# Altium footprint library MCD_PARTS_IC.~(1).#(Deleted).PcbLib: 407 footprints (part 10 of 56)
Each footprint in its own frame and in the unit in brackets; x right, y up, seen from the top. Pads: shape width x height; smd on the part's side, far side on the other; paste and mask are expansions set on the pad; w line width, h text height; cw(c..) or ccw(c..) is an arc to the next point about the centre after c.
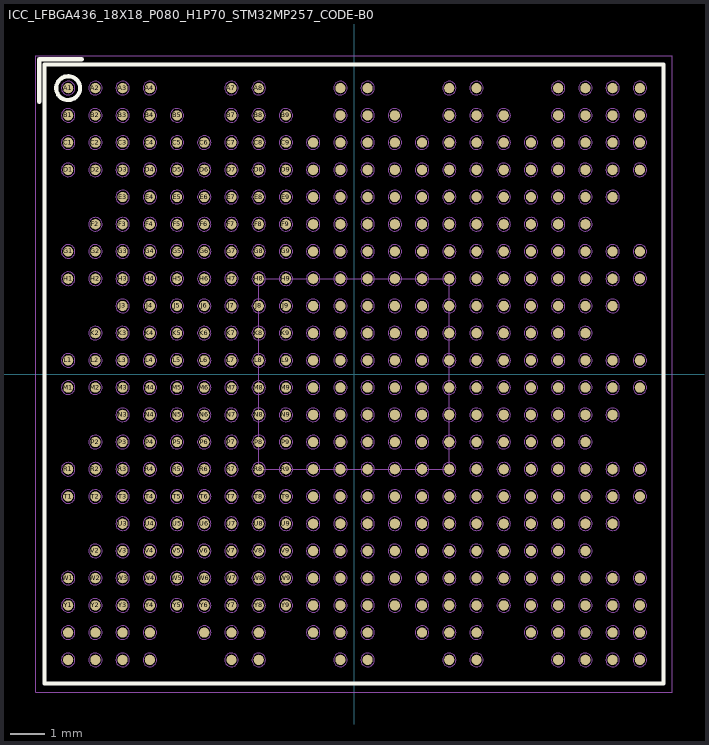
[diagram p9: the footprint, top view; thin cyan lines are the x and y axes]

## ICC_LFBGA436_18X18_P080_H1P70_STM32MP257_CODE-B0D1 [mm] "MCD02000"
height 1.7
pads (436):
  round 0.3 smd paste+0.025 mask+0.05: A1(-8.4,8.4) A2(-7.6,8.4) A3(-6.8,8.4) A4(-6,8.4) A7(-3.6,8.4) A8(-2.8,8.4) A11(-0.4,8.4) A12(0.4,8.4) A15(2.8,8.4) A16(3.6,8.4) A19(6,8.4) A20(6.8,8.4) A21(7.6,8.4) A22(8.4,8.4) AA1(-8.4,-7.6) AA2(-7.6,-7.6) AA3(-6.8,-7.6) AA4(-6,-7.6) AA6(-4.4,-7.6) AA7(-3.6,-7.6) AA8(-2.8,-7.6) AA10(-1.2,-7.6) AA11(-0.4,-7.6) AA12(0.4,-7.6) AA14(2,-7.6) AA15(2.8,-7.6) AA16(3.6,-7.6) AA18(5.2,-7.6) AA19(6,-7.6) AA20(6.8,-7.6) AA21(7.6,-7.6) AA22(8.4,-7.6) AB1(-8.4,-8.4) AB2(-7.6,-8.4) AB3(-6.8,-8.4) AB4(-6,-8.4) AB7(-3.6,-8.4) AB8(-2.8,-8.4) AB11(-0.4,-8.4) AB12(0.4,-8.4) AB15(2.8,-8.4) AB16(3.6,-8.4) AB19(6,-8.4) AB20(6.8,-8.4) AB21(7.6,-8.4) AB22(8.4,-8.4) B1(-8.4,7.6) B2(-7.6,7.6) B3(-6.8,7.6) B4(-6,7.6) B5(-5.2,7.6) B7(-3.6,7.6) B8(-2.8,7.6) B9(-2,7.6) B11(-0.4,7.6) B12(0.4,7.6) B13(1.2,7.6) B15(2.8,7.6) B16(3.6,7.6) B17(4.4,7.6) B19(6,7.6) B20(6.8,7.6) B21(7.6,7.6) B22(8.4,7.6) C1(-8.4,6.8) C2(-7.6,6.8) C3(-6.8,6.8) C4(-6,6.8) C5(-5.2,6.8) C6(-4.4,6.8) C7(-3.6,6.8) C8(-2.8,6.8) C9(-2,6.8) C10(-1.2,6.8) C11(-0.4,6.8) C12(0.4,6.8) C13(1.2,6.8) C14(2,6.8) C15(2.8,6.8) C16(3.6,6.8) C17(4.4,6.8) C18(5.2,6.8) C19(6,6.8) C20(6.8,6.8) C21(7.6,6.8) C22(8.4,6.8) D1(-8.4,6) D2(-7.6,6) D3(-6.8,6) D4(-6,6) D5(-5.2,6) D6(-4.4,6) D7(-3.6,6) D8(-2.8,6) D9(-2,6) D10(-1.2,6) D11(-0.4,6) D12(0.4,6) D13(1.2,6) D14(2,6) D15(2.8,6) D16(3.6,6) D17(4.4,6) D18(5.2,6) D19(6,6) D20(6.8,6) D21(7.6,6) D22(8.4,6) E3(-6.8,5.2) E4(-6,5.2) E5(-5.2,5.2) E6(-4.4,5.2) E7(-3.6,5.2) E8(-2.8,5.2) E9(-2,5.2) E10(-1.2,5.2) E11(-0.4,5.2) E12(0.4,5.2) E13(1.2,5.2) E14(2,5.2) E15(2.8,5.2) E16(3.6,5.2) E17(4.4,5.2) E18(5.2,5.2) E19(6,5.2) E20(6.8,5.2) E21(7.6,5.2) F2(-7.6,4.4) F3(-6.8,4.4) F4(-6,4.4) F5(-5.2,4.4) F6(-4.4,4.4) F7(-3.6,4.4) F8(-2.8,4.4) F9(-2,4.4) F10(-1.2,4.4) F11(-0.4,4.4) F12(0.4,4.4) F13(1.2,4.4) F14(2,4.4) F15(2.8,4.4) F16(3.6,4.4) F17(4.4,4.4) F18(5.2,4.4) F19(6,4.4) F20(6.8,4.4) G1(-8.4,3.6) G2(-7.6,3.6) G3(-6.8,3.6) G4(-6,3.6) G5(-5.2,3.6) G6(-4.4,3.6) G7(-3.6,3.6) G8(-2.8,3.6) G9(-2,3.6) G10(-1.2,3.6) G11(-0.4,3.6) G12(0.4,3.6) G13(1.2,3.6) G14(2,3.6) G15(2.8,3.6) G16(3.6,3.6) G17(4.4,3.6) G18(5.2,3.6) G19(6,3.6) G20(6.8,3.6) G21(7.6,3.6) G22(8.4,3.6) H1(-8.4,2.8) H2(-7.6,2.8) H3(-6.8,2.8) H4(-6,2.8) H5(-5.2,2.8) H6(-4.4,2.8) H7(-3.6,2.8) H8(-2.8,2.8) H9(-2,2.8) H10(-1.2,2.8) H11(-0.4,2.8) H12(0.4,2.8) H13(1.2,2.8) H14(2,2.8) H15(2.8,2.8) H16(3.6,2.8) H17(4.4,2.8) H18(5.2,2.8) H19(6,2.8) H20(6.8,2.8) H21(7.6,2.8) H22(8.4,2.8) J3(-6.8,2) J4(-6,2) J5(-5.2,2) J6(-4.4,2) J7(-3.6,2) J8(-2.8,2) J9(-2,2) J10(-1.2,2) J11(-0.4,2) J12(0.4,2) J13(1.2,2) J14(2,2) J15(2.8,2) J16(3.6,2) J17(4.4,2) J18(5.2,2) J19(6,2) J20(6.8,2) J21(7.6,2) K2(-7.6,1.2) K3(-6.8,1.2) K4(-6,1.2) K5(-5.2,1.2) K6(-4.4,1.2) K7(-3.6,1.2) K8(-2.8,1.2) K9(-2,1.2) K10(-1.2,1.2) K11(-0.4,1.2) K12(0.4,1.2) K13(1.2,1.2) K14(2,1.2) K15(2.8,1.2) K16(3.6,1.2) K17(4.4,1.2) K18(5.2,1.2) K19(6,1.2) K20(6.8,1.2) L1(-8.4,0.4) L2(-7.6,0.4) L3(-6.8,0.4) L4(-6,0.4) L5(-5.2,0.4) L6(-4.4,0.4) L7(-3.6,0.4) L8(-2.8,0.4) L9(-2,0.4) L10(-1.2,0.4) L11(-0.4,0.4) L12(0.4,0.4) L13(1.2,0.4) L14(2,0.4) L15(2.8,0.4) L16(3.6,0.4) L17(4.4,0.4) L18(5.2,0.4) L19(6,0.4) L20(6.8,0.4) L21(7.6,0.4) L22(8.4,0.4) M1(-8.4,-0.4) M2(-7.6,-0.4) M3(-6.8,-0.4) M4(-6,-0.4) M5(-5.2,-0.4) M6(-4.4,-0.4) M7(-3.6,-0.4) M8(-2.8,-0.4) M9(-2,-0.4) M10(-1.2,-0.4) M11(-0.4,-0.4) M12(0.4,-0.4) M13(1.2,-0.4) M14(2,-0.4) M15(2.8,-0.4) M16(3.6,-0.4) M17(4.4,-0.4) M18(5.2,-0.4) M19(6,-0.4) M20(6.8,-0.4) M21(7.6,-0.4) M22(8.4,-0.4) N3(-6.8,-1.2) N4(-6,-1.2) N5(-5.2,-1.2) N6(-4.4,-1.2) N7(-3.6,-1.2) N8(-2.8,-1.2) N9(-2,-1.2) N10(-1.2,-1.2) N11(-0.4,-1.2) N12(0.4,-1.2) N13(1.2,-1.2) N14(2,-1.2) N15(2.8,-1.2) N16(3.6,-1.2) N17(4.4,-1.2) N18(5.2,-1.2) N19(6,-1.2) N20(6.8,-1.2) N21(7.6,-1.2) P2(-7.6,-2) P3(-6.8,-2) P4(-6,-2) P5(-5.2,-2) P6(-4.4,-2) P7(-3.6,-2) P8(-2.8,-2) P9(-2,-2) P10(-1.2,-2) P11(-0.4,-2) P12(0.4,-2) P13(1.2,-2) P14(2,-2) P15(2.8,-2) P16(3.6,-2) P17(4.4,-2) P18(5.2,-2) P19(6,-2) P20(6.8,-2) R1(-8.4,-2.8) R2(-7.6,-2.8) R3(-6.8,-2.8) R4(-6,-2.8) R5(-5.2,-2.8) R6(-4.4,-2.8) R7(-3.6,-2.8) R8(-2.8,-2.8) R9(-2,-2.8) R10(-1.2,-2.8) R11(-0.4,-2.8) R12(0.4,-2.8) R13(1.2,-2.8) R14(2,-2.8) R15(2.8,-2.8) R16(3.6,-2.8) R17(4.4,-2.8) R18(5.2,-2.8) R19(6,-2.8) R20(6.8,-2.8) R21(7.6,-2.8) R22(8.4,-2.8) T1(-8.4,-3.6) T2(-7.6,-3.6) T3(-6.8,-3.6) T4(-6,-3.6) T5(-5.2,-3.6) T6(-4.4,-3.6) T7(-3.6,-3.6) T8(-2.8,-3.6) T9(-2,-3.6) T10(-1.2,-3.6) T11(-0.4,-3.6) T12(0.4,-3.6) T13(1.2,-3.6) T14(2,-3.6) T15(2.8,-3.6) T16(3.6,-3.6) T17(4.4,-3.6) T18(5.2,-3.6) T19(6,-3.6) T20(6.8,-3.6) T21(7.6,-3.6) T22(8.4,-3.6) U3(-6.8,-4.4) U4(-6,-4.4) U5(-5.2,-4.4) U6(-4.4,-4.4) U7(-3.6,-4.4) U8(-2.8,-4.4) U9(-2,-4.4) U10(-1.2,-4.4) U11(-0.4,-4.4) U12(0.4,-4.4) U13(1.2,-4.4) U14(2,-4.4) U15(2.8,-4.4) U16(3.6,-4.4) U17(4.4,-4.4) U18(5.2,-4.4) U19(6,-4.4) U20(6.8,-4.4) U21(7.6,-4.4) V2(-7.6,-5.2) V3(-6.8,-5.2) V4(-6,-5.2) V5(-5.2,-5.2) V6(-4.4,-5.2) V7(-3.6,-5.2) V8(-2.8,-5.2) V9(-2,-5.2) V10(-1.2,-5.2) V11(-0.4,-5.2) V12(0.4,-5.2) V13(1.2,-5.2) V14(2,-5.2) V15(2.8,-5.2) V16(3.6,-5.2) V17(4.4,-5.2) V18(5.2,-5.2) V19(6,-5.2) V20(6.8,-5.2) W1(-8.4,-6) W2(-7.6,-6) W3(-6.8,-6) W4(-6,-6) W5(-5.2,-6) W6(-4.4,-6) W7(-3.6,-6) W8(-2.8,-6) W9(-2,-6) W10(-1.2,-6) W11(-0.4,-6) W12(0.4,-6) W13(1.2,-6) W14(2,-6) W15(2.8,-6) W16(3.6,-6) W17(4.4,-6) W18(5.2,-6) W19(6,-6) W20(6.8,-6) W21(7.6,-6) W22(8.4,-6) Y1(-8.4,-6.8) Y2(-7.6,-6.8) Y3(-6.8,-6.8) Y4(-6,-6.8) Y5(-5.2,-6.8) Y6(-4.4,-6.8) Y7(-3.6,-6.8) Y8(-2.8,-6.8) Y9(-2,-6.8) Y10(-1.2,-6.8) Y11(-0.4,-6.8) Y12(0.4,-6.8) Y13(1.2,-6.8) Y14(2,-6.8) Y15(2.8,-6.8) Y16(3.6,-6.8) Y17(4.4,-6.8) Y18(5.2,-6.8) Y19(6,-6.8) Y20(6.8,-6.8) Y21(7.6,-6.8) Y22(8.4,-6.8)
Top Overlay:
  circle w0.12: c-8.4,8.4 r0.35
  lines w0.12: -9.25,8 -9.25,9.25 -8,9.25 ; -9.1,-9.1 -9.1,9.1 9.1,9.1 9.1,-9.1 -9.1,-9.1
M14-Top Assembly:
  drawing of 444 lines, arcs and shapes, not listed
  text "'.Designator'" at -2,-0.2 h0.75
  text "A1" at -8.65,8.2 h0.4
  text "A22" at 7.875,8.2 h0.4
  text "AB22" at 7.7,-8.6 h0.4
  text "AB1" at -8.8,-8.6 h0.4
M16-Top Courtyard:
  lines w0.01: -9.35,-9.35 -9.35,9.35 9.35,9.35 9.35,-9.35 -9.35,-9.35
3D body: height 1.11, standoff 1.1, extent -8.697,8.101 -8.1,8.7
3D body: height 0.36, standoff -0.04, extent 2.601,4.203 3,4.597
3D body: height 0.36, standoff -0.04, extent 1.801,4.203 2.2,4.597
3D body: height 0.36, standoff -0.04, extent 1.001,4.203 1.4,4.597
3D body: height 0.36, standoff -0.04, extent 0.201,4.203 0.6,4.597
3D body: height 0.36, standoff -0.04, extent -0.599,4.203 -0.2,4.597
3D body: height 0.36, standoff -0.04, extent -4.599,4.203 -4.2,4.597
3D body: height 0.36, standoff -0.04, extent -3.799,4.203 -3.4,4.597
3D body: height 0.36, standoff -0.04, extent -2.999,4.203 -2.6,4.597
3D body: height 0.36, standoff -0.04, extent -2.199,4.203 -1.8,4.597
3D body: height 0.36, standoff -0.04, extent -1.399,4.203 -1,4.597
3D body: height 0.36, standoff -0.04, extent -7.799,4.203 -7.4,4.597
3D body: height 0.36, standoff -0.04, extent -6.999,4.203 -6.6,4.597
3D body: height 0.36, standoff -0.04, extent -6.199,4.203 -5.8,4.597
3D body: height 0.36, standoff -0.04, extent -5.399,4.203 -5,4.597
3D body: height 0.36, standoff -0.04, extent 2.601,5.003 3,5.397
3D body: height 0.36, standoff -0.04, extent 1.801,5.003 2.2,5.397
3D body: height 0.36, standoff -0.04, extent 1.001,5.003 1.4,5.397
3D body: height 0.36, standoff -0.04, extent 0.201,5.003 0.6,5.397
3D body: height 0.36, standoff -0.04, extent -0.599,5.003 -0.2,5.397
3D body: height 0.36, standoff -0.04, extent -4.599,5.003 -4.2,5.397
3D body: height 0.36, standoff -0.04, extent -3.799,5.003 -3.4,5.397
3D body: height 0.36, standoff -0.04, extent -2.999,5.003 -2.6,5.397
3D body: height 0.36, standoff -0.04, extent -2.199,5.003 -1.8,5.397
3D body: height 0.36, standoff -0.04, extent -1.399,5.003 -1,5.397
3D body: height 0.36, standoff -0.04, extent -6.999,5.003 -6.6,5.397
3D body: height 0.36, standoff -0.04, extent -6.199,5.003 -5.8,5.397
3D body: height 0.36, standoff -0.04, extent -5.399,5.003 -5,5.397
3D body: height 0.36, standoff -0.04, extent 2.601,5.803 3,6.197
3D body: height 0.36, standoff -0.04, extent 1.801,5.803 2.2,6.197
3D body: height 0.36, standoff -0.04, extent 1.001,5.803 1.4,6.197
3D body: height 0.36, standoff -0.04, extent 0.201,5.803 0.6,6.197
3D body: height 0.36, standoff -0.04, extent -0.599,5.803 -0.2,6.197
3D body: height 0.36, standoff -0.04, extent -4.599,5.803 -4.2,6.197
3D body: height 0.36, standoff -0.04, extent -3.799,5.803 -3.4,6.197
3D body: height 0.36, standoff -0.04, extent -2.999,5.803 -2.6,6.197
3D body: height 0.36, standoff -0.04, extent -2.199,5.803 -1.8,6.197
3D body: height 0.36, standoff -0.04, extent -1.399,5.803 -1,6.197
3D body: height 0.36, standoff -0.04, extent -8.599,5.803 -8.2,6.197
3D body: height 0.36, standoff -0.04, extent -7.799,5.803 -7.4,6.197
3D body: height 0.36, standoff -0.04, extent -6.999,5.803 -6.6,6.197
3D body: height 0.36, standoff -0.04, extent -6.199,5.803 -5.8,6.197
3D body: height 0.36, standoff -0.04, extent -5.399,5.803 -5,6.197
3D body: height 0.36, standoff -0.04, extent 2.601,6.603 3,6.997
3D body: height 0.36, standoff -0.04, extent 1.801,6.603 2.2,6.997
3D body: height 0.36, standoff -0.04, extent 1.001,6.603 1.4,6.997
3D body: height 0.36, standoff -0.04, extent 0.201,6.603 0.6,6.997
3D body: height 0.36, standoff -0.04, extent -0.599,6.603 -0.2,6.997
3D body: height 0.36, standoff -0.04, extent -4.599,6.603 -4.2,6.997
3D body: height 0.36, standoff -0.04, extent -3.799,6.603 -3.4,6.997
3D body: height 0.36, standoff -0.04, extent -2.999,6.603 -2.6,6.997
3D body: height 0.36, standoff -0.04, extent -2.199,6.603 -1.8,6.997
3D body: height 0.36, standoff -0.04, extent -1.399,6.603 -1,6.997
3D body: height 0.36, standoff -0.04, extent -8.599,6.603 -8.2,6.997
3D body: height 0.36, standoff -0.04, extent -7.799,6.603 -7.4,6.997
3D body: height 0.36, standoff -0.04, extent -6.999,6.603 -6.6,6.997
3D body: height 0.36, standoff -0.04, extent -6.199,6.603 -5.8,6.997
3D body: height 0.36, standoff -0.04, extent -5.399,6.603 -5,6.997
3D body: height 0.36, standoff -0.04, extent 2.601,7.403 3,7.797
3D body: height 0.36, standoff -0.04, extent 1.001,7.403 1.4,7.797
3D body: height 0.36, standoff -0.04, extent 0.201,7.403 0.6,7.797
3D body: height 0.36, standoff -0.04, extent -0.599,7.403 -0.2,7.797
3D body: height 0.36, standoff -0.04, extent -3.799,7.403 -3.4,7.797
3D body: height 0.36, standoff -0.04, extent -2.999,7.403 -2.6,7.797
3D body: height 0.36, standoff -0.04, extent -2.199,7.403 -1.8,7.797
3D body: height 0.36, standoff -0.04, extent -8.599,7.403 -8.2,7.797
3D body: height 0.36, standoff -0.04, extent -7.799,7.403 -7.4,7.797
3D body: height 0.36, standoff -0.04, extent -6.999,7.403 -6.6,7.797
3D body: height 0.36, standoff -0.04, extent -6.199,7.403 -5.8,7.797
3D body: height 0.36, standoff -0.04, extent -5.399,7.403 -5,7.797
3D body: height 0.36, standoff -0.04, extent -8.599,8.203 -8.2,8.597
3D body: height 0.36, standoff -0.04, extent -6.199,8.203 -5.8,8.597
3D body: height 0.36, standoff -0.04, extent -6.999,8.203 -6.6,8.597
3D body: height 0.36, standoff -0.04, extent -7.799,8.203 -7.4,8.597
3D body: height 0.36, standoff -0.04, extent -2.999,8.203 -2.6,8.597
3D body: height 0.36, standoff -0.04, extent -3.799,8.203 -3.4,8.597
3D body: height 0.36, standoff -0.04, extent -0.599,8.203 -0.2,8.597
3D body: height 0.36, standoff -0.04, extent 0.201,8.203 0.6,8.597
3D body: height 0.36, standoff -0.04, extent 2.601,8.203 3,8.597
3D body: height 0.36, standoff -0.04, extent 4.201,4.203 4.6,4.597
3D body: height 0.36, standoff -0.04, extent 5.001,4.203 5.4,4.597
3D body: height 0.36, standoff -0.04, extent 5.801,4.203 6.2,4.597
3D body: height 0.36, standoff -0.04, extent 3.401,5.003 3.8,5.397
3D body: height 0.36, standoff -0.04, extent 4.201,5.003 4.6,5.397
3D body: height 0.36, standoff -0.04, extent 5.001,5.003 5.4,5.397
3D body: height 0.36, standoff -0.04, extent 3.401,5.803 3.8,6.197
3D body: height 0.36, standoff -0.04, extent 4.201,5.803 4.6,6.197
3D body: height 0.36, standoff -0.04, extent 5.001,5.803 5.4,6.197
3D body: height 0.36, standoff -0.04, extent 5.801,5.803 6.2,6.197
3D body: height 0.36, standoff -0.04, extent 3.401,6.603 3.8,6.997
3D body: height 0.36, standoff -0.04, extent 4.201,6.603 4.6,6.997
3D body: height 0.36, standoff -0.04, extent 5.001,6.603 5.4,6.997
3D body: height 0.36, standoff -0.04, extent 5.801,6.603 6.2,6.997
3D body: height 0.36, standoff -0.04, extent 3.401,7.403 3.8,7.797
3D body: height 0.36, standoff -0.04, extent 4.201,7.403 4.6,7.797
3D body: height 0.36, standoff -0.04, extent 5.801,7.403 6.2,7.797
3D body: height 0.36, standoff -0.04, extent 5.801,8.203 6.2,8.597
3D body: height 0.36, standoff -0.04, extent 3.401,8.203 3.8,8.597
3D body: height 0.36, standoff -0.04, extent 2.601,-0.597 3,-0.203
3D body: height 0.36, standoff -0.04, extent 1.801,-0.597 2.2,-0.203
3D body: height 0.36, standoff -0.04, extent 1.001,-0.597 1.4,-0.203
3D body: height 0.36, standoff -0.04, extent 0.201,-0.597 0.6,-0.203
3D body: height 0.36, standoff -0.04, extent -0.599,-0.597 -0.2,-0.203
3D body: height 0.36, standoff -0.04, extent -4.599,-0.597 -4.2,-0.203
3D body: height 0.36, standoff -0.04, extent -3.799,-0.597 -3.4,-0.203
3D body: height 0.36, standoff -0.04, extent -2.999,-0.597 -2.6,-0.203
3D body: height 0.36, standoff -0.04, extent -2.199,-0.597 -1.8,-0.203
3D body: height 0.36, standoff -0.04, extent -1.399,-0.597 -1,-0.203
3D body: height 0.36, standoff -0.04, extent -8.599,-0.597 -8.2,-0.203
3D body: height 0.36, standoff -0.04, extent -7.799,-0.597 -7.4,-0.203
3D body: height 0.36, standoff -0.04, extent -6.999,-0.597 -6.6,-0.203
3D body: height 0.36, standoff -0.04, extent -6.199,-0.597 -5.8,-0.203
3D body: height 0.36, standoff -0.04, extent -5.399,-0.597 -5,-0.203
3D body: height 0.36, standoff -0.04, extent 2.601,0.203 3,0.597
3D body: height 0.36, standoff -0.04, extent 1.801,0.203 2.2,0.597
3D body: height 0.36, standoff -0.04, extent 1.001,0.203 1.4,0.597
3D body: height 0.36, standoff -0.04, extent 0.201,0.203 0.6,0.597
3D body: height 0.36, standoff -0.04, extent -0.599,0.203 -0.2,0.597
3D body: height 0.36, standoff -0.04, extent -4.599,0.203 -4.2,0.597
3D body: height 0.36, standoff -0.04, extent -3.799,0.203 -3.4,0.597
3D body: height 0.36, standoff -0.04, extent -2.999,0.203 -2.6,0.597
3D body: height 0.36, standoff -0.04, extent -2.199,0.203 -1.8,0.597
3D body: height 0.36, standoff -0.04, extent -1.399,0.203 -1,0.597
3D body: height 0.36, standoff -0.04, extent -8.599,0.203 -8.2,0.597
3D body: height 0.36, standoff -0.04, extent -7.799,0.203 -7.4,0.597
3D body: height 0.36, standoff -0.04, extent -6.999,0.203 -6.6,0.597
3D body: height 0.36, standoff -0.04, extent -6.199,0.203 -5.8,0.597
3D body: height 0.36, standoff -0.04, extent -5.399,0.203 -5,0.597
3D body: height 0.36, standoff -0.04, extent 2.601,1.003 3,1.397
3D body: height 0.36, standoff -0.04, extent 1.801,1.003 2.2,1.397
3D body: height 0.36, standoff -0.04, extent 1.001,1.003 1.4,1.397
3D body: height 0.36, standoff -0.04, extent 0.201,1.003 0.6,1.397
3D body: height 0.36, standoff -0.04, extent -0.599,1.003 -0.2,1.397
3D body: height 0.36, standoff -0.04, extent -4.599,1.003 -4.2,1.397
3D body: height 0.36, standoff -0.04, extent -3.799,1.003 -3.4,1.397
3D body: height 0.36, standoff -0.04, extent -2.999,1.003 -2.6,1.397
3D body: height 0.36, standoff -0.04, extent -2.199,1.003 -1.8,1.397
3D body: height 0.36, standoff -0.04, extent -1.399,1.003 -1,1.397
3D body: height 0.36, standoff -0.04, extent -7.799,1.003 -7.4,1.397
3D body: height 0.36, standoff -0.04, extent -6.999,1.003 -6.6,1.397
3D body: height 0.36, standoff -0.04, extent -6.199,1.003 -5.8,1.397
3D body: height 0.36, standoff -0.04, extent -5.399,1.003 -5,1.397
3D body: height 0.36, standoff -0.04, extent 2.601,1.803 3,2.197
3D body: height 0.36, standoff -0.04, extent 1.801,1.803 2.2,2.197
3D body: height 0.36, standoff -0.04, extent 1.001,1.803 1.4,2.197
3D body: height 0.36, standoff -0.04, extent 0.201,1.803 0.6,2.197
3D body: height 0.36, standoff -0.04, extent -0.599,1.803 -0.2,2.197
3D body: height 0.36, standoff -0.04, extent -4.599,1.803 -4.2,2.197
3D body: height 0.36, standoff -0.04, extent -3.799,1.803 -3.4,2.197
3D body: height 0.36, standoff -0.04, extent -2.999,1.803 -2.6,2.197
3D body: height 0.36, standoff -0.04, extent -2.199,1.803 -1.8,2.197
3D body: height 0.36, standoff -0.04, extent -1.399,1.803 -1,2.197
3D body: height 0.36, standoff -0.04, extent -6.999,1.803 -6.6,2.197
3D body: height 0.36, standoff -0.04, extent -6.199,1.803 -5.8,2.197
3D body: height 0.36, standoff -0.04, extent -5.399,1.803 -5,2.197
3D body: height 0.36, standoff -0.04, extent 2.601,2.603 3,2.997
3D body: height 0.36, standoff -0.04, extent 1.801,2.603 2.2,2.997
3D body: height 0.36, standoff -0.04, extent 1.001,2.603 1.4,2.997
3D body: height 0.36, standoff -0.04, extent 0.201,2.603 0.6,2.997
3D body: height 0.36, standoff -0.04, extent -0.599,2.603 -0.2,2.997
3D body: height 0.36, standoff -0.04, extent -4.599,2.603 -4.2,2.997
3D body: height 0.36, standoff -0.04, extent -3.799,2.603 -3.4,2.997
3D body: height 0.36, standoff -0.04, extent -2.999,2.603 -2.6,2.997
3D body: height 0.36, standoff -0.04, extent -2.199,2.603 -1.8,2.997
3D body: height 0.36, standoff -0.04, extent -1.399,2.603 -1,2.997
3D body: height 0.36, standoff -0.04, extent -8.599,2.603 -8.2,2.997
3D body: height 0.36, standoff -0.04, extent -7.799,2.603 -7.4,2.997
3D body: height 0.36, standoff -0.04, extent -6.999,2.603 -6.6,2.997
3D body: height 0.36, standoff -0.04, extent -6.199,2.603 -5.8,2.997
3D body: height 0.36, standoff -0.04, extent -5.399,2.603 -5,2.997
3D body: height 0.36, standoff -0.04, extent -5.399,3.403 -5,3.797
3D body: height 0.36, standoff -0.04, extent -6.199,3.403 -5.8,3.797
3D body: height 0.36, standoff -0.04, extent -6.999,3.403 -6.6,3.797
3D body: height 0.36, standoff -0.04, extent -7.799,3.403 -7.4,3.797
3D body: height 0.36, standoff -0.04, extent -8.599,3.403 -8.2,3.797
3D body: height 0.36, standoff -0.04, extent -1.399,3.403 -1,3.797
3D body: height 0.36, standoff -0.04, extent -2.199,3.403 -1.8,3.797
3D body: height 0.36, standoff -0.04, extent -2.999,3.403 -2.6,3.797
3D body: height 0.36, standoff -0.04, extent -3.799,3.403 -3.4,3.797
3D body: height 0.36, standoff -0.04, extent -4.599,3.403 -4.2,3.797
3D body: height 0.36, standoff -0.04, extent -0.599,3.403 -0.2,3.797
3D body: height 0.36, standoff -0.04, extent 0.201,3.403 0.6,3.797
3D body: height 0.36, standoff -0.04, extent 1.001,3.403 1.4,3.797
3D body: height 0.36, standoff -0.04, extent 1.801,3.403 2.2,3.797
3D body: height 0.36, standoff -0.04, extent 2.601,3.403 3,3.797
3D body: height 0.36, standoff -0.04, extent 2.601,-5.397 3,-5.003
3D body: height 0.36, standoff -0.04, extent 1.801,-5.397 2.2,-5.003
3D body: height 0.36, standoff -0.04, extent 1.001,-5.397 1.4,-5.003
3D body: height 0.36, standoff -0.04, extent 0.201,-5.397 0.6,-5.003
3D body: height 0.36, standoff -0.04, extent -0.599,-5.397 -0.2,-5.003
3D body: height 0.36, standoff -0.04, extent -4.599,-5.397 -4.2,-5.003
3D body: height 0.36, standoff -0.04, extent -3.799,-5.397 -3.4,-5.003
3D body: height 0.36, standoff -0.04, extent -2.999,-5.397 -2.6,-5.003
3D body: height 0.36, standoff -0.04, extent -2.199,-5.397 -1.8,-5.003
3D body: height 0.36, standoff -0.04, extent -1.399,-5.397 -1,-5.003
3D body: height 0.36, standoff -0.04, extent -7.799,-5.397 -7.4,-5.003
3D body: height 0.36, standoff -0.04, extent -6.999,-5.397 -6.6,-5.003
3D body: height 0.36, standoff -0.04, extent -6.199,-5.397 -5.8,-5.003
3D body: height 0.36, standoff -0.04, extent -5.399,-5.397 -5,-5.003
3D body: height 0.36, standoff -0.04, extent 2.601,-4.597 3,-4.203
3D body: height 0.36, standoff -0.04, extent 1.801,-4.597 2.2,-4.203
3D body: height 0.36, standoff -0.04, extent 1.001,-4.597 1.4,-4.203
3D body: height 0.36, standoff -0.04, extent 0.201,-4.597 0.6,-4.203
3D body: height 0.36, standoff -0.04, extent -0.599,-4.597 -0.2,-4.203
3D body: height 0.36, standoff -0.04, extent -4.599,-4.597 -4.2,-4.203
3D body: height 0.36, standoff -0.04, extent -3.799,-4.597 -3.4,-4.203
3D body: height 0.36, standoff -0.04, extent -2.999,-4.597 -2.6,-4.203
3D body: height 0.36, standoff -0.04, extent -2.199,-4.597 -1.8,-4.203
3D body: height 0.36, standoff -0.04, extent -1.399,-4.597 -1,-4.203
3D body: height 0.36, standoff -0.04, extent -6.999,-4.597 -6.6,-4.203
3D body: height 0.36, standoff -0.04, extent -6.199,-4.597 -5.8,-4.203
3D body: height 0.36, standoff -0.04, extent -5.399,-4.597 -5,-4.203
3D body: height 0.36, standoff -0.04, extent 2.601,-3.797 3,-3.403
3D body: height 0.36, standoff -0.04, extent 1.801,-3.797 2.2,-3.403
3D body: height 0.36, standoff -0.04, extent 1.001,-3.797 1.4,-3.403
3D body: height 0.36, standoff -0.04, extent 0.201,-3.797 0.6,-3.403
3D body: height 0.36, standoff -0.04, extent -0.599,-3.797 -0.2,-3.403
3D body: height 0.36, standoff -0.04, extent -4.599,-3.797 -4.2,-3.403
3D body: height 0.36, standoff -0.04, extent -3.799,-3.797 -3.4,-3.403
3D body: height 0.36, standoff -0.04, extent -2.999,-3.797 -2.6,-3.403
3D body: height 0.36, standoff -0.04, extent -2.199,-3.797 -1.8,-3.403
3D body: height 0.36, standoff -0.04, extent -1.399,-3.797 -1,-3.403
3D body: height 0.36, standoff -0.04, extent -8.599,-3.797 -8.2,-3.403
3D body: height 0.36, standoff -0.04, extent -7.799,-3.797 -7.4,-3.403
3D body: height 0.36, standoff -0.04, extent -6.999,-3.797 -6.6,-3.403
3D body: height 0.36, standoff -0.04, extent -6.199,-3.797 -5.8,-3.403
3D body: height 0.36, standoff -0.04, extent -5.399,-3.797 -5,-3.403
3D body: height 0.36, standoff -0.04, extent 2.601,-2.997 3,-2.603
3D body: height 0.36, standoff -0.04, extent 1.801,-2.997 2.2,-2.603
3D body: height 0.36, standoff -0.04, extent 1.001,-2.997 1.4,-2.603
3D body: height 0.36, standoff -0.04, extent 0.201,-2.997 0.6,-2.603
3D body: height 0.36, standoff -0.04, extent -0.599,-2.997 -0.2,-2.603
3D body: height 0.36, standoff -0.04, extent -4.599,-2.997 -4.2,-2.603
3D body: height 0.36, standoff -0.04, extent -3.799,-2.997 -3.4,-2.603
3D body: height 0.36, standoff -0.04, extent -2.999,-2.997 -2.6,-2.603
3D body: height 0.36, standoff -0.04, extent -2.199,-2.997 -1.8,-2.603
3D body: height 0.36, standoff -0.04, extent -1.399,-2.997 -1,-2.603
3D body: height 0.36, standoff -0.04, extent -8.599,-2.997 -8.2,-2.603
3D body: height 0.36, standoff -0.04, extent -7.799,-2.997 -7.4,-2.603
3D body: height 0.36, standoff -0.04, extent -6.999,-2.997 -6.6,-2.603
3D body: height 0.36, standoff -0.04, extent -6.199,-2.997 -5.8,-2.603
3D body: height 0.36, standoff -0.04, extent -5.399,-2.997 -5,-2.603
3D body: height 0.36, standoff -0.04, extent 2.601,-2.197 3,-1.803
3D body: height 0.36, standoff -0.04, extent 1.801,-2.197 2.2,-1.803
3D body: height 0.36, standoff -0.04, extent 1.001,-2.197 1.4,-1.803
3D body: height 0.36, standoff -0.04, extent 0.201,-2.197 0.6,-1.803
3D body: height 0.36, standoff -0.04, extent -0.599,-2.197 -0.2,-1.803
3D body: height 0.36, standoff -0.04, extent -4.599,-2.197 -4.2,-1.803
3D body: height 0.36, standoff -0.04, extent -3.799,-2.197 -3.4,-1.803
3D body: height 0.36, standoff -0.04, extent -2.999,-2.197 -2.6,-1.803
3D body: height 0.36, standoff -0.04, extent -2.199,-2.197 -1.8,-1.803
3D body: height 0.36, standoff -0.04, extent -1.399,-2.197 -1,-1.803
3D body: height 0.36, standoff -0.04, extent -7.799,-2.197 -7.4,-1.803
3D body: height 0.36, standoff -0.04, extent -6.999,-2.197 -6.6,-1.803
3D body: height 0.36, standoff -0.04, extent -6.199,-2.197 -5.8,-1.803
3D body: height 0.36, standoff -0.04, extent -5.399,-2.197 -5,-1.803
3D body: height 0.36, standoff -0.04, extent -5.399,-1.397 -5,-1.003
3D body: height 0.36, standoff -0.04, extent -6.199,-1.397 -5.8,-1.003
3D body: height 0.36, standoff -0.04, extent -6.999,-1.397 -6.6,-1.003
3D body: height 0.36, standoff -0.04, extent -1.399,-1.397 -1,-1.003
3D body: height 0.36, standoff -0.04, extent -2.199,-1.397 -1.8,-1.003
3D body: height 0.36, standoff -0.04, extent -2.999,-1.397 -2.6,-1.003
3D body: height 0.36, standoff -0.04, extent -3.799,-1.397 -3.4,-1.003
3D body: height 0.36, standoff -0.04, extent -4.599,-1.397 -4.2,-1.003
3D body: height 0.36, standoff -0.04, extent -0.599,-1.397 -0.2,-1.003
3D body: height 0.36, standoff -0.04, extent 0.201,-1.397 0.6,-1.003
3D body: height 0.36, standoff -0.04, extent 1.001,-1.397 1.4,-1.003
3D body: height 0.36, standoff -0.04, extent 1.801,-1.397 2.2,-1.003
3D body: height 0.36, standoff -0.04, extent 2.601,-1.397 3,-1.003
3D body: height 0.36, standoff -0.04, extent -5.399,-6.197 -5,-5.803
3D body: height 0.36, standoff -0.04, extent -6.199,-6.197 -5.8,-5.803
3D body: height 0.36, standoff -0.04, extent -6.999,-6.197 -6.6,-5.803
3D body: height 0.36, standoff -0.04, extent -7.799,-6.197 -7.4,-5.803
3D body: height 0.36, standoff -0.04, extent -8.599,-6.197 -8.2,-5.803
3D body: height 0.36, standoff -0.04, extent -1.399,-6.197 -1,-5.803
3D body: height 0.36, standoff -0.04, extent -2.199,-6.197 -1.8,-5.803
3D body: height 0.36, standoff -0.04, extent -2.999,-6.197 -2.6,-5.803
3D body: height 0.36, standoff -0.04, extent -3.799,-6.197 -3.4,-5.803
3D body: height 0.36, standoff -0.04, extent -4.599,-6.197 -4.2,-5.803
3D body: height 0.36, standoff -0.04, extent -0.599,-6.197 -0.2,-5.803
3D body: height 0.36, standoff -0.04, extent 0.201,-6.197 0.6,-5.803
3D body: height 0.36, standoff -0.04, extent 1.001,-6.197 1.4,-5.803
3D body: height 0.36, standoff -0.04, extent 1.801,-6.197 2.2,-5.803
3D body: height 0.36, standoff -0.04, extent 2.601,-6.197 3,-5.803
3D body: height 0.36, standoff -0.04, extent 4.201,-0.597 4.6,-0.203
3D body: height 0.36, standoff -0.04, extent 5.001,-0.597 5.4,-0.203
3D body: height 0.36, standoff -0.04, extent 5.801,-0.597 6.2,-0.203
3D body: height 0.36, standoff -0.04, extent 3.401,0.203 3.8,0.597
3D body: height 0.36, standoff -0.04, extent 4.201,0.203 4.6,0.597
3D body: height 0.36, standoff -0.04, extent 5.001,0.203 5.4,0.597
3D body: height 0.36, standoff -0.04, extent 5.801,0.203 6.2,0.597
3D body: height 0.36, standoff -0.04, extent 4.201,1.003 4.6,1.397
3D body: height 0.36, standoff -0.04, extent 5.001,1.003 5.4,1.397
3D body: height 0.36, standoff -0.04, extent 5.801,1.003 6.2,1.397
3D body: height 0.36, standoff -0.04, extent 3.401,1.803 3.8,2.197
3D body: height 0.36, standoff -0.04, extent 4.201,1.803 4.6,2.197
3D body: height 0.36, standoff -0.04, extent 5.001,1.803 5.4,2.197
3D body: height 0.36, standoff -0.04, extent 5.801,1.803 6.2,2.197
3D body: height 0.36, standoff -0.04, extent 4.201,2.603 4.6,2.997
3D body: height 0.36, standoff -0.04, extent 5.001,2.603 5.4,2.997
3D body: height 0.36, standoff -0.04, extent 5.801,2.603 6.2,2.997
3D body: height 0.36, standoff -0.04, extent 5.801,3.403 6.2,3.797
3D body: height 0.36, standoff -0.04, extent 5.001,3.403 5.4,3.797
3D body: height 0.36, standoff -0.04, extent 4.201,3.403 4.6,3.797
3D body: height 0.36, standoff -0.04, extent 3.401,3.403 3.8,3.797
3D body: height 0.36, standoff -0.04, extent 3.401,-5.397 3.8,-5.003
3D body: height 0.36, standoff -0.04, extent 4.201,-5.397 4.6,-5.003
3D body: height 0.36, standoff -0.04, extent 5.001,-5.397 5.4,-5.003
3D body: height 0.36, standoff -0.04, extent 5.801,-5.397 6.2,-5.003
3D body: height 0.36, standoff -0.04, extent 3.401,-4.597 3.8,-4.203
3D body: height 0.36, standoff -0.04, extent 4.201,-4.597 4.6,-4.203
3D body: height 0.36, standoff -0.04, extent 5.001,-4.597 5.4,-4.203
3D body: height 0.36, standoff -0.04, extent 5.801,-4.597 6.2,-4.203
3D body: height 0.36, standoff -0.04, extent 3.401,-3.797 3.8,-3.403
3D body: height 0.36, standoff -0.04, extent 4.201,-3.797 4.6,-3.403
3D body: height 0.36, standoff -0.04, extent 5.001,-3.797 5.4,-3.403
3D body: height 0.36, standoff -0.04, extent 5.801,-3.797 6.2,-3.403
3D body: height 0.36, standoff -0.04, extent 3.401,-2.997 3.8,-2.603
3D body: height 0.36, standoff -0.04, extent 4.201,-2.997 4.6,-2.603
3D body: height 0.36, standoff -0.04, extent 5.001,-2.997 5.4,-2.603
3D body: height 0.36, standoff -0.04, extent 4.201,-2.197 4.6,-1.803
3D body: height 0.36, standoff -0.04, extent 5.001,-2.197 5.4,-1.803
3D body: height 0.36, standoff -0.04, extent 5.801,-2.197 6.2,-1.803
3D body: height 0.36, standoff -0.04, extent 5.801,-1.397 6.2,-1.003
3D body: height 0.36, standoff -0.04, extent 5.001,-1.397 5.4,-1.003
3D body: height 0.36, standoff -0.04, extent 4.201,-1.397 4.6,-1.003
3D body: height 0.36, standoff -0.04, extent 3.401,-1.397 3.8,-1.003
3D body: height 0.36, standoff -0.04, extent 5.801,-6.197 6.2,-5.803
3D body: height 0.36, standoff -0.04, extent 5.001,-6.197 5.4,-5.803
3D body: height 0.36, standoff -0.04, extent 4.201,-6.197 4.6,-5.803
3D body: height 0.36, standoff -0.04, extent 3.401,-6.197 3.8,-5.803
3D body: height 0.36, standoff -0.04, extent 7.401,8.203 7.8,8.597
3D body: height 0.36, standoff -0.04, extent 8.201,8.203 8.6,8.597
3D body: height 0.36, standoff -0.04, extent 8.201,7.403 8.6,7.797
3D body: height 0.36, standoff -0.04, extent 7.401,7.403 7.8,7.797
3D body: height 0.36, standoff -0.04, extent 8.201,6.603 8.6,6.997
3D body: height 0.36, standoff -0.04, extent 7.401,6.603 7.8,6.997
3D body: height 0.36, standoff -0.04, extent 8.201,5.803 8.6,6.197
3D body: height 0.36, standoff -0.04, extent 7.401,5.803 7.8,6.197
3D body: height 0.36, standoff -0.04, extent 6.601,8.203 7,8.597
3D body: height 0.36, standoff -0.04, extent 6.601,7.403 7,7.797
3D body: height 0.36, standoff -0.04, extent 6.601,6.603 7,6.997
3D body: height 0.36, standoff -0.04, extent 6.601,5.803 7,6.197
3D body: height 0.36, standoff -0.04, extent 7.401,5.003 7.8,5.397
3D body: height 0.36, standoff -0.04, extent 8.201,3.403 8.6,3.797
3D body: height 0.36, standoff -0.04, extent 7.401,3.403 7.8,3.797
3D body: height 0.36, standoff -0.04, extent 8.201,2.603 8.6,2.997
3D body: height 0.36, standoff -0.04, extent 7.401,2.603 7.8,2.997
3D body: height 0.36, standoff -0.04, extent 6.601,5.003 7,5.397
3D body: height 0.36, standoff -0.04, extent 6.601,4.203 7,4.597
3D body: height 0.36, standoff -0.04, extent 6.601,3.403 7,3.797
3D body: height 0.36, standoff -0.04, extent 6.601,2.603 7,2.997
3D body: height 0.36, standoff -0.04, extent 7.401,1.803 7.8,2.197
3D body: height 0.36, standoff -0.04, extent 8.201,0.203 8.6,0.597
3D body: height 0.36, standoff -0.04, extent 7.401,0.203 7.8,0.597
3D body: height 0.36, standoff -0.04, extent 8.201,-0.597 8.6,-0.203
3D body: height 0.36, standoff -0.04, extent 7.401,-0.597 7.8,-0.203
3D body: height 0.36, standoff -0.04, extent 6.601,1.803 7,2.197
3D body: height 0.36, standoff -0.04, extent 6.601,1.003 7,1.397
3D body: height 0.36, standoff -0.04, extent 6.601,0.203 7,0.597
3D body: height 0.36, standoff -0.04, extent 6.601,-0.597 7,-0.203
3D body: height 0.36, standoff -0.04, extent 7.401,-1.397 7.8,-1.003
3D body: height 0.36, standoff -0.04, extent 8.201,-2.997 8.6,-2.603
3D body: height 0.36, standoff -0.04, extent 7.401,-2.997 7.8,-2.603
3D body: height 0.36, standoff -0.04, extent 8.201,-3.797 8.6,-3.403
3D body: height 0.36, standoff -0.04, extent 7.401,-3.797 7.8,-3.403
3D body: height 0.36, standoff -0.04, extent 6.601,-1.397 7,-1.003
3D body: height 0.36, standoff -0.04, extent 6.601,-2.197 7,-1.803
3D body: height 0.36, standoff -0.04, extent 6.601,-2.997 7,-2.603
3D body: height 0.36, standoff -0.04, extent 6.601,-3.797 7,-3.403
3D body: height 0.36, standoff -0.04, extent 7.401,-4.597 7.8,-4.203
3D body: height 0.36, standoff -0.04, extent 8.201,-6.197 8.6,-5.803
3D body: height 0.36, standoff -0.04, extent 7.401,-6.197 7.8,-5.803
3D body: height 0.36, standoff -0.04, extent 8.201,-6.997 8.6,-6.603
3D body: height 0.36, standoff -0.04, extent 7.401,-6.997 7.8,-6.603
3D body: height 0.36, standoff -0.04, extent 6.601,-4.597 7,-4.203
3D body: height 0.36, standoff -0.04, extent 6.601,-5.397 7,-5.003
3D body: height 0.36, standoff -0.04, extent 6.601,-6.197 7,-5.803
3D body: height 0.36, standoff -0.04, extent 6.601,-6.997 7,-6.603
3D body: height 0.36, standoff -0.04, extent 7.401,-7.797 7.8,-7.403
3D body: height 0.36, standoff -0.04, extent 8.201,-7.797 8.6,-7.403
3D body: height 0.36, standoff -0.04, extent 8.201,-8.597 8.6,-8.203
3D body: height 0.36, standoff -0.04, extent 7.401,-8.597 7.8,-8.203
3D body: height 0.36, standoff -0.04, extent 6.601,-7.797 7,-7.403
3D body: height 0.36, standoff -0.04, extent 6.601,-8.597 7,-8.203
3D body: height 0.36, standoff -0.04, extent 5.803,-7.8 6.197,-7.401
3D body: height 0.36, standoff -0.04, extent 5.803,-8.6 6.197,-8.201
3D body: height 0.36, standoff -0.04, extent 5.003,-7.8 5.397,-7.401
3D body: height 0.36, standoff -0.04, extent 3.403,-8.6 3.797,-8.201
3D body: height 0.36, standoff -0.04, extent 3.403,-7.8 3.797,-7.401
3D body: height 0.36, standoff -0.04, extent 5.803,-7 6.197,-6.601
3D body: height 0.36, standoff -0.04, extent 5.003,-7 5.397,-6.601
3D body: height 0.36, standoff -0.04, extent 4.203,-7 4.597,-6.601
3D body: height 0.36, standoff -0.04, extent 3.403,-7 3.797,-6.601
3D body: height 0.36, standoff -0.04, extent 2.603,-7.8 2.997,-7.401
3D body: height 0.36, standoff -0.04, extent 2.603,-8.6 2.997,-8.201
3D body: height 0.36, standoff -0.04, extent 1.803,-7.8 2.197,-7.401
3D body: height 0.36, standoff -0.04, extent 0.203,-8.6 0.597,-8.201
3D body: height 0.36, standoff -0.04, extent 0.203,-7.8 0.597,-7.401
3D body: height 0.36, standoff -0.04, extent 2.603,-7 2.997,-6.601
3D body: height 0.36, standoff -0.04, extent 1.803,-7 2.197,-6.601
3D body: height 0.36, standoff -0.04, extent 1.003,-7 1.397,-6.601
3D body: height 0.36, standoff -0.04, extent 0.203,-7 0.597,-6.601
3D body: height 0.36, standoff -0.04, extent -0.597,-7.8 -0.203,-7.401
3D body: height 0.36, standoff -0.04, extent -0.597,-8.6 -0.203,-8.201
3D body: height 0.36, standoff -0.04, extent -1.397,-7.8 -1.003,-7.401
3D body: height 0.36, standoff -0.04, extent -2.997,-8.6 -2.603,-8.201
3D body: height 0.36, standoff -0.04, extent -2.997,-7.8 -2.603,-7.401
3D body: height 0.36, standoff -0.04, extent -0.597,-7 -0.203,-6.601
3D body: height 0.36, standoff -0.04, extent -1.397,-7 -1.003,-6.601
3D body: height 0.36, standoff -0.04, extent -2.197,-7 -1.803,-6.601
3D body: height 0.36, standoff -0.04, extent -2.997,-7 -2.603,-6.601
3D body: height 0.36, standoff -0.04, extent -3.797,-7.8 -3.403,-7.401
3D body: height 0.36, standoff -0.04, extent -3.797,-8.6 -3.403,-8.201
3D body: height 0.36, standoff -0.04, extent -4.597,-7.8 -4.203,-7.401
3D body: height 0.36, standoff -0.04, extent -6.197,-8.6 -5.803,-8.201
3D body: height 0.36, standoff -0.04, extent -6.197,-7.8 -5.803,-7.401
3D body: height 0.36, standoff -0.04, extent -3.797,-7 -3.403,-6.601
3D body: height 0.36, standoff -0.04, extent -4.597,-7 -4.203,-6.601
3D body: height 0.36, standoff -0.04, extent -5.397,-7 -5.003,-6.601
3D body: height 0.36, standoff -0.04, extent -6.197,-7 -5.803,-6.601
3D body: height 0.36, standoff -0.04, extent -6.997,-7.8 -6.603,-7.401
3D body: height 0.36, standoff -0.04, extent -6.997,-8.6 -6.603,-8.201
3D body: height 0.36, standoff -0.04, extent -7.797,-8.6 -7.403,-8.201
3D body: height 0.36, standoff -0.04, extent -7.797,-7.8 -7.403,-7.401
3D body: height 0.36, standoff -0.04, extent -8.597,-8.6 -8.203,-8.201
3D body: height 0.36, standoff -0.04, extent -8.597,-7.8 -8.203,-7.401
3D body: height 0.36, standoff -0.04, extent -6.997,-7 -6.603,-6.601
3D body: height 0.36, standoff -0.04, extent -7.797,-7 -7.403,-6.601
3D body: height 0.36, standoff -0.04, extent -8.597,-7 -8.203,-6.601
3D body: height 0.36, standoff -0.04, extent 5.801,5.003 6.2,5.397
3D body: height 0.36, standoff -0.04, extent 3.401,4.203 3.8,4.597
3D body: height 0.36, standoff -0.04, extent 3.401,2.603 3.8,2.997
3D body: height 0.36, standoff -0.04, extent 3.401,1.003 3.8,1.397
3D body: height 0.36, standoff -0.04, extent 3.401,-0.597 3.8,-0.203
3D body: height 0.36, standoff -0.04, extent 3.401,-2.197 3.8,-1.803
3D body: height 0.36, standoff -0.04, extent 5.801,-2.997 6.2,-2.603
3D body: height 1.1, standoff 0.29, extent -9.1,-9.1 9.1,9.1
3D body: height 1.7, standoff 1.1, extent -2.8,-2.8 2.8,2.8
